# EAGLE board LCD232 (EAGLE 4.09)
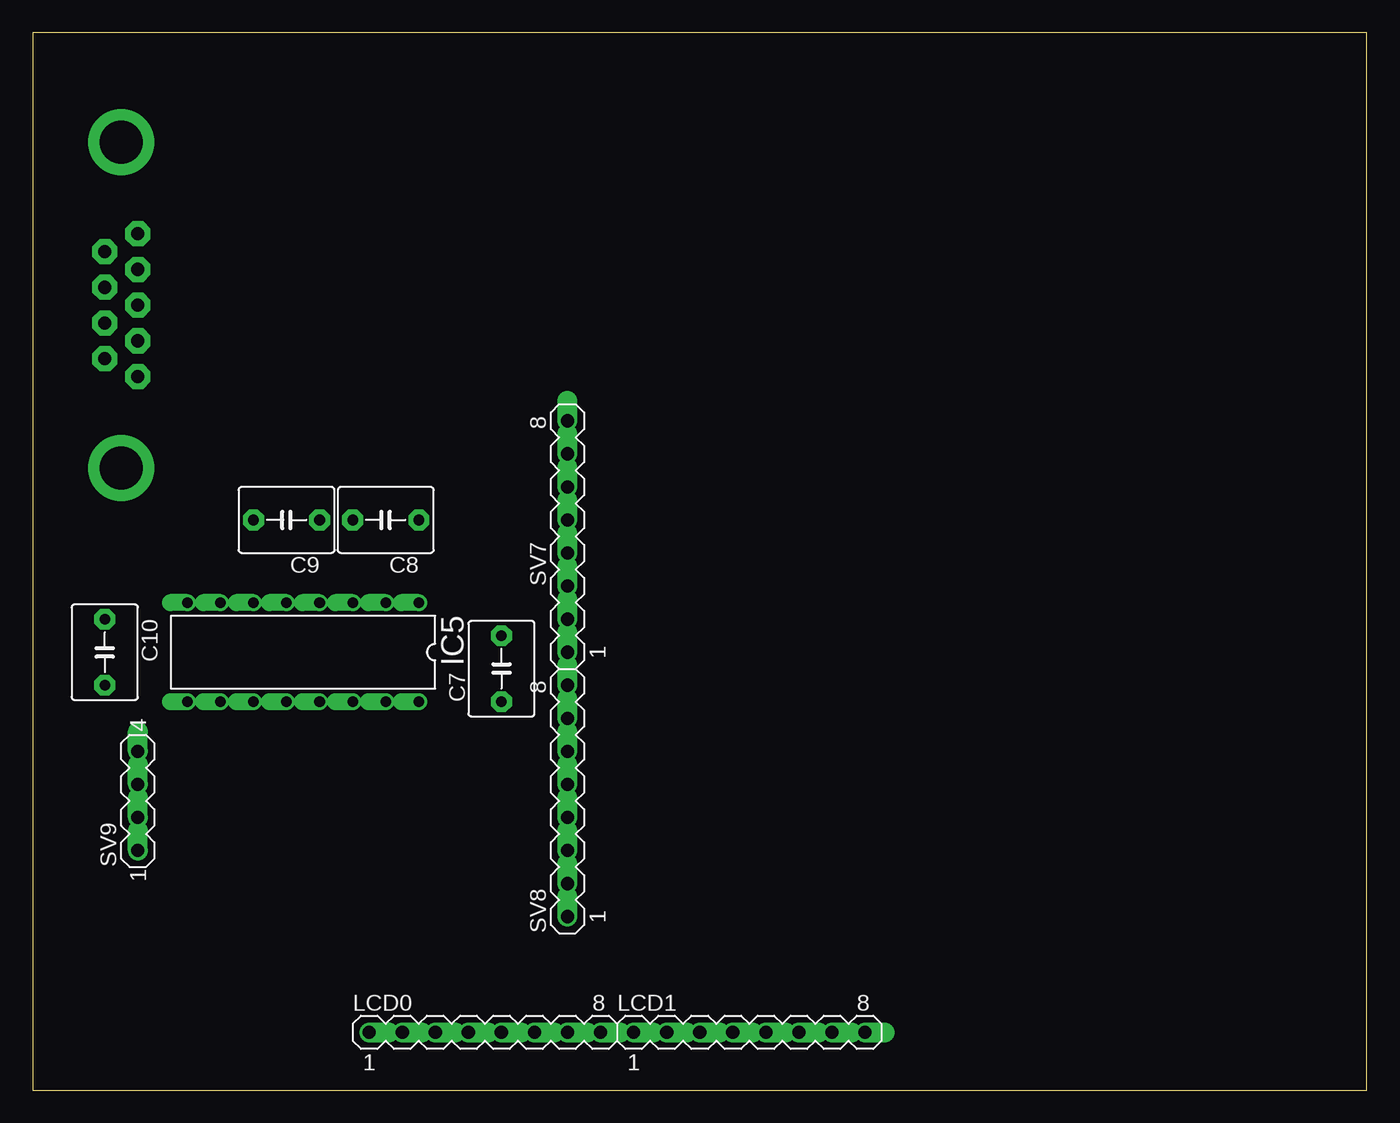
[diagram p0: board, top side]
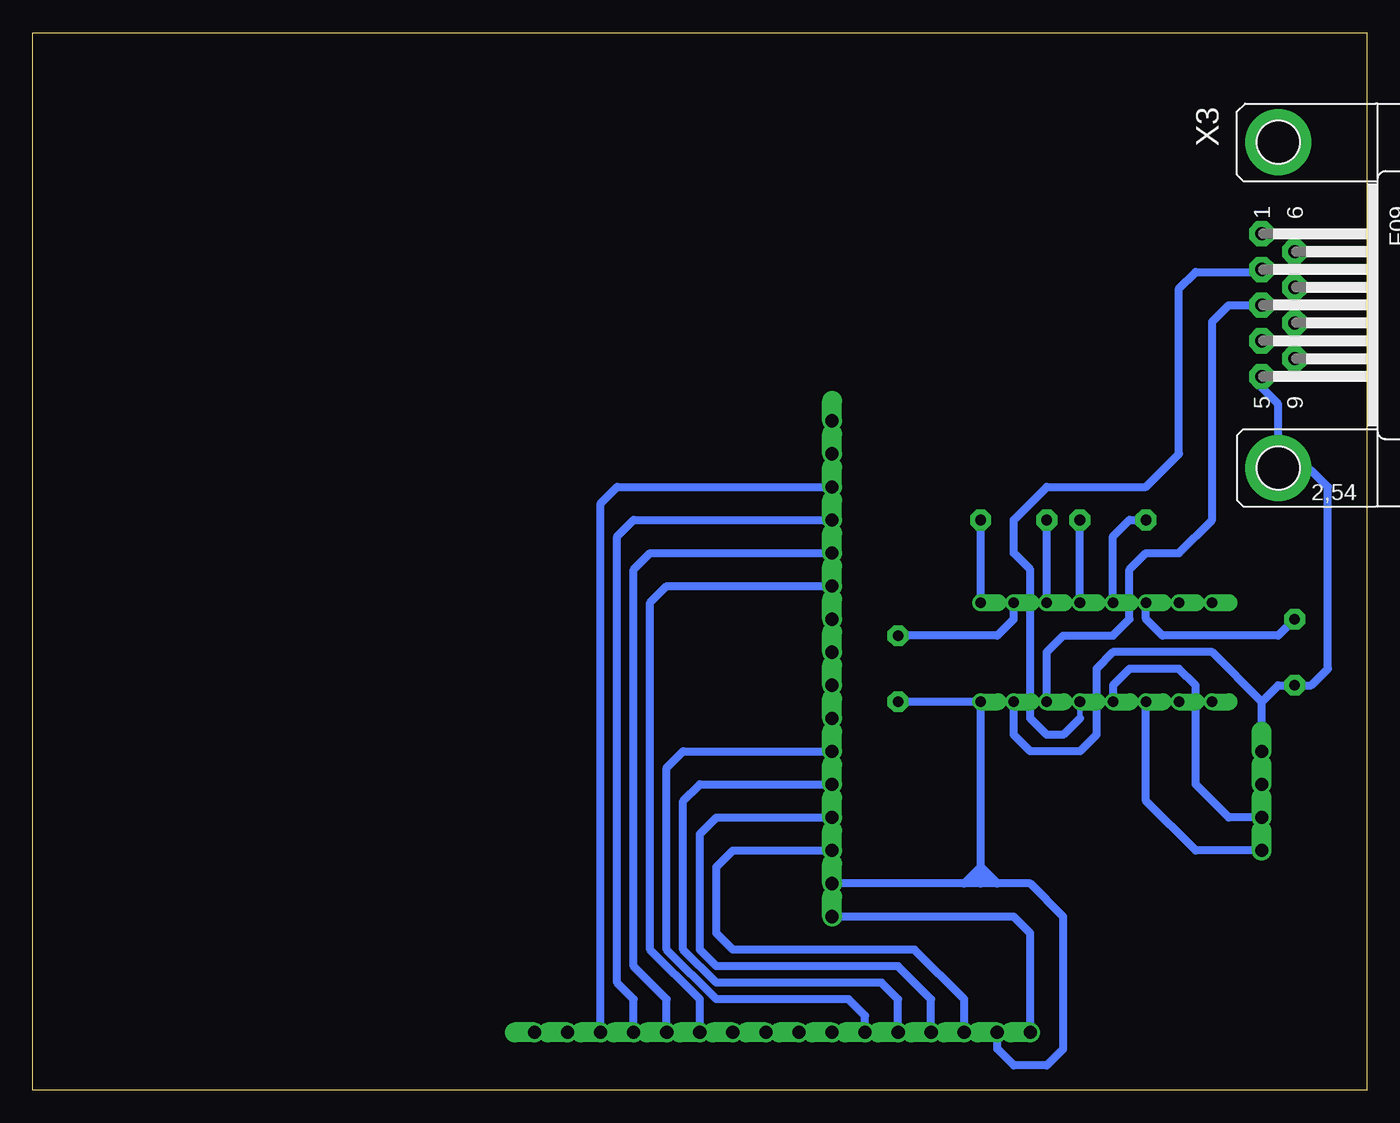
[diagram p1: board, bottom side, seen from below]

Size 102.54 x 81.27 mm. Coordinates in mm from the lower left corner, seen from the top.
Outline: 0,0 102.54,0 102.54,81.27 0,81.27 0,0
Copper layers used: Bottom
tKeepout: area 15.7,10.8 to 20.8,15.9

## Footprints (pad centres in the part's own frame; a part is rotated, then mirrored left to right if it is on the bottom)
C5B5 = drill 0.813 pad 1.6 octagon: 1 -2.54,0; 2 2.54,0
DIL16 = drill 0.813 offset: 1 -8.89,-3.81; 2 -6.35,-3.81; 3 -3.81,-3.81; 4 -1.27,-3.81; 5 1.27,-3.81; 6 3.81,-3.81; 7 6.35,-3.81; 8 8.89,-3.81; 9 8.89,3.81; 10 6.35,3.81; 11 3.81,3.81; 12 1.27,3.81; 13 -1.27,3.81; 14 -3.81,3.81; 15 -6.35,3.81; 16 -8.89,3.81
MA08-1 = drill 1.016 offset: 1 -8.89,0; 2 -6.35,0; 3 -3.81,0; 4 -1.27,0; 5 1.27,0; 6 3.81,0; 7 6.35,0; 8 8.89,0
MA04-1 = drill 1.016 offset: 1 -3.81,0; 2 -1.27,0; 3 1.27,0; 4 3.81,0
F09HP = drill 1.016 pad 1.93 octagon: 1 -5.486,-1.27; 2 -2.743,-1.27; 3 0,-1.27; 4 2.743,-1.27; 5 5.486,-1.27; 6 -4.115,1.27; 7 -1.372,1.27; 8 1.372,1.27; 9 4.115,1.27 | drill 3.302 pad 5.08 round: G1 -12.522,0; G2 12.522,0

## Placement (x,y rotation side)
C7  [C5B5]  36.03,32.38 90 top
C8  [C5B5]  27.14,43.81 180 top
C9  [C5B5]  19.52,43.81 180 top
C10  [C5B5]  5.55,33.65 270 top
IC5  MAX232  [DIL16]  20.79,33.65 180 top
LCD0  [MA08-1]  34.76,4.44 0 top
LCD1  [MA08-1]  55.08,4.44 0 top
SV7  [MA08-1]  41.11,42.54 90 top
SV8  [MA08-1]  41.11,22.22 90 top
SV9  [MA04-1]  8.09,22.22 90 top
X3  [F09HP]  6.82,60.32 270 bottom

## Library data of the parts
C7-C10 = capacitor-wima
IC5 = maxim
LCD0 LCD1 SV7-SV9 = con-lstb
X3 = con-subd

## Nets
+5V: C7.1 IC5.16 LCD0.2 SV8.2
N$1: C10.2 IC5.15 SV9.4 X3.5 X3.G2
N$3: LCD0.5 SV8.5
N$4: LCD0.1 SV8.1
N$14: LCD1.6 SV7.6
N$17: LCD1.5 SV7.5
N$18: LCD1.4 SV7.4
N$19: LCD1.3 SV7.3
N$20: LCD0.3 SV8.3
N$25: LCD0.6 SV8.6
N$26: LCD0.4 SV8.4
N$54: C10.1 IC5.6
N$55: C7.2 IC5.2
N$57: C8.1 IC5.1
N$58: IC5.13 X3.2
N$59: C8.2 IC5.3
N$60: C9.1 IC5.4
N$61: IC5.12 SV9.2
N$62: IC5.14 X3.3
N$64: IC5.11 SV9.1
N$65: C9.2 IC5.5

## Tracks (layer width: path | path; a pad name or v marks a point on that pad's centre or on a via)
+5V
  Bottom 0.61: C7.1 IC5.16 29.68,17.14 | 29.68,17.14 30.95,15.87 | 30.95,15.87 SV8.2 | LCD0.2 28.41,3.17 27.14,1.9 24.6,1.9 23.33,3.17 23.33,13.33 25.87,15.87 28.41,15.87 | 28.41,15.87 29.68,15.87 | 29.68,15.87 30.95,15.87 | 28.41,15.87 29.68,17.14 | 29.68,15.87 29.68,17.14
N$1
  Bottom 0.406: 8.09,55.24 X3.5 | 6.82,47.62 X3.G2
  Bottom 0.61: 8.09,55.24 8.09,53.97 6.82,52.7 X3.G2 | IC5.15 27.14,27.3 25.87,26.03 22.06,26.03 20.79,27.3 20.79,32.38 19.52,33.65 11.9,33.65 8.09,29.84 | 6.82,47.62 4.28,47.62 3.01,46.35 3.01,32.38 4.28,31.11 6.82,31.11 | 6.82,31.11 C10.2 | 8.09,29.84 6.82,31.11 | SV9.4 8.09,29.84
N$3
  Bottom 0.61: LCD0.5 36.03,6.98 37.3,8.25 50,8.25 52.54,10.79 52.54,22.22 51.27,23.49 SV8.5
N$4
  Bottom 0.61: LCD0.1 25.87,12.06 27.14,13.33 SV8.1
N$14
  Bottom 0.61: LCD1.6 58.89,45.08 57.62,46.35 SV7.6
N$17
  Bottom 0.61: LCD1.5 56.35,6.98 57.62,8.25 57.62,42.54 56.35,43.81 SV7.5
N$18
  Bottom 0.61: LCD1.4 53.81,6.98 56.35,9.52 56.35,40 55.08,41.27 SV7.4
N$19
  Bottom 0.61: LCD1.3 51.27,6.98 55.08,10.79 55.08,37.46 53.81,38.73 SV7.3
N$20
  Bottom 0.61: LCD0.3 30.95,6.98 34.76,10.79 48.73,10.79 50,12.06 50,17.14 48.73,18.41 SV8.3
N$25
  Bottom 0.61: LCD0.6 38.57,5.71 39.84,6.98 50,6.98 53.81,10.79 53.81,24.76 52.54,26.03 SV8.6
N$26
  Bottom 0.61: LCD0.4 33.49,6.98 36.03,9.52 50,9.52 51.27,10.79 51.27,19.68 50,20.95 SV8.4
N$54
  Bottom 0.61: IC5.6 16.98,36.19 15.71,34.92 6.82,34.92 C10.1
N$55
  Bottom 0.61: C7.2 28.41,34.92 27.14,36.19 IC5.2
N$57
  Bottom 0.61: IC5.1 C8.1
N$58
  Bottom 0.406: 22.06,28.57 IC5.13 | 8.09,62.86 X3.2
  Bottom 0.61: 22.06,28.57 23.33,27.3 24.6,27.3 25.87,28.57 25.87,40 27.14,41.27 27.14,43.81 24.6,46.35 16.98,46.35 14.44,48.89 14.44,61.59 13.17,62.86 8.09,62.86
N$59
  Bottom 0.61: IC5.3 C8.2
N$60
  Bottom 0.61: IC5.4 C9.1
N$61
  Bottom 0.61: SV9.2 10.63,20.95 13.17,23.49 13.17,31.11 14.44,32.38 18.25,32.38 19.52,31.11 IC5.12
N$62
  Bottom 0.61: IC5.14 24.6,33.65 23.33,34.92 19.52,34.92 18.25,36.19 18.25,40 16.98,41.27 14.44,41.27 11.9,43.81 11.9,59.05 10.63,60.32 X3.3
N$64
  Bottom 0.61: SV9.1 13.17,18.41 16.98,22.22 IC5.11
N$65
  Bottom 0.61: IC5.5 19.52,42.54 18.25,43.81 C9.2
S$1
  Bottom 0.813: 29.17,16.38 29.93,16.38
